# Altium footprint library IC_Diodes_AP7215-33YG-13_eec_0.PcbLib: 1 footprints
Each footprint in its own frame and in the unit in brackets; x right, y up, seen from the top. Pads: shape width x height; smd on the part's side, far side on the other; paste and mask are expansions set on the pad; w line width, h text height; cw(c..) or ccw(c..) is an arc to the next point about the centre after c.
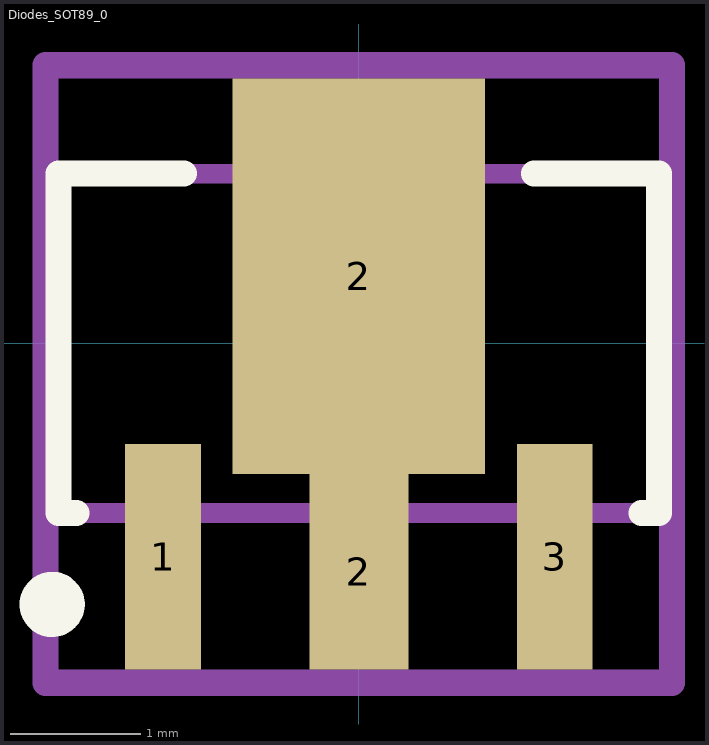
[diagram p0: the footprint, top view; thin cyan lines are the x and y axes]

## Diodes_SOT89_0 [mm]
pads (4):
  rect 0.58x1.73 smd paste+0 mask+0: 1(-1.5,-1.635) 3(1.5,-1.635)
  rect 0.76x1.5 smd paste+0 mask+0: 2(0,-1.75)
  rect 1.933x3.03 smd paste+0 mask+0: 2(0,0.515)
Top Overlay:
  circle w0.25: c-2.35,-2 r0.125
  lines w0.2: -2.165,-1.3 -2.3,-1.3 -2.3,1.3 -1.342,1.3 ; 1.342,1.3 2.3,1.3 2.3,-1.3 2.165,-1.3
Mechanical 10:
  lines w0.2: -2.4,-2.6 2.4,-2.6 2.4,2.13 -2.4,2.13 -2.4,-2.6
  text ".Designator" at 0,-0.235 h1
Mechanical 12:
  lines w0.15: -2.3,-1.3 2.3,-1.3 2.3,1.3 -2.3,1.3 -2.3,-1.3
Mechanical 15:
  lines w0.1: -0.5,0 0.5,0 ; 0,-0.5 0,0.5
  lines w0.2: -2.4,-2.6 2.4,-2.6 2.4,2.13 -2.4,2.13 -2.4,-2.6
3D body "IC_Diodes_AP7215-33YG-13_eec.STEP": height 0.25, standoff 0, extent -2.4,-2.6 2.4,2.13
